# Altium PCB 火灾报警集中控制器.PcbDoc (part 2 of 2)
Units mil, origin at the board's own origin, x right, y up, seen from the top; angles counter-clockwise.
Board outline 3890 x 3920 mil, 2 copper layers (Top Layer, Bottom Layer); 74 components, 132 nets, 502 pads, 181 vias.
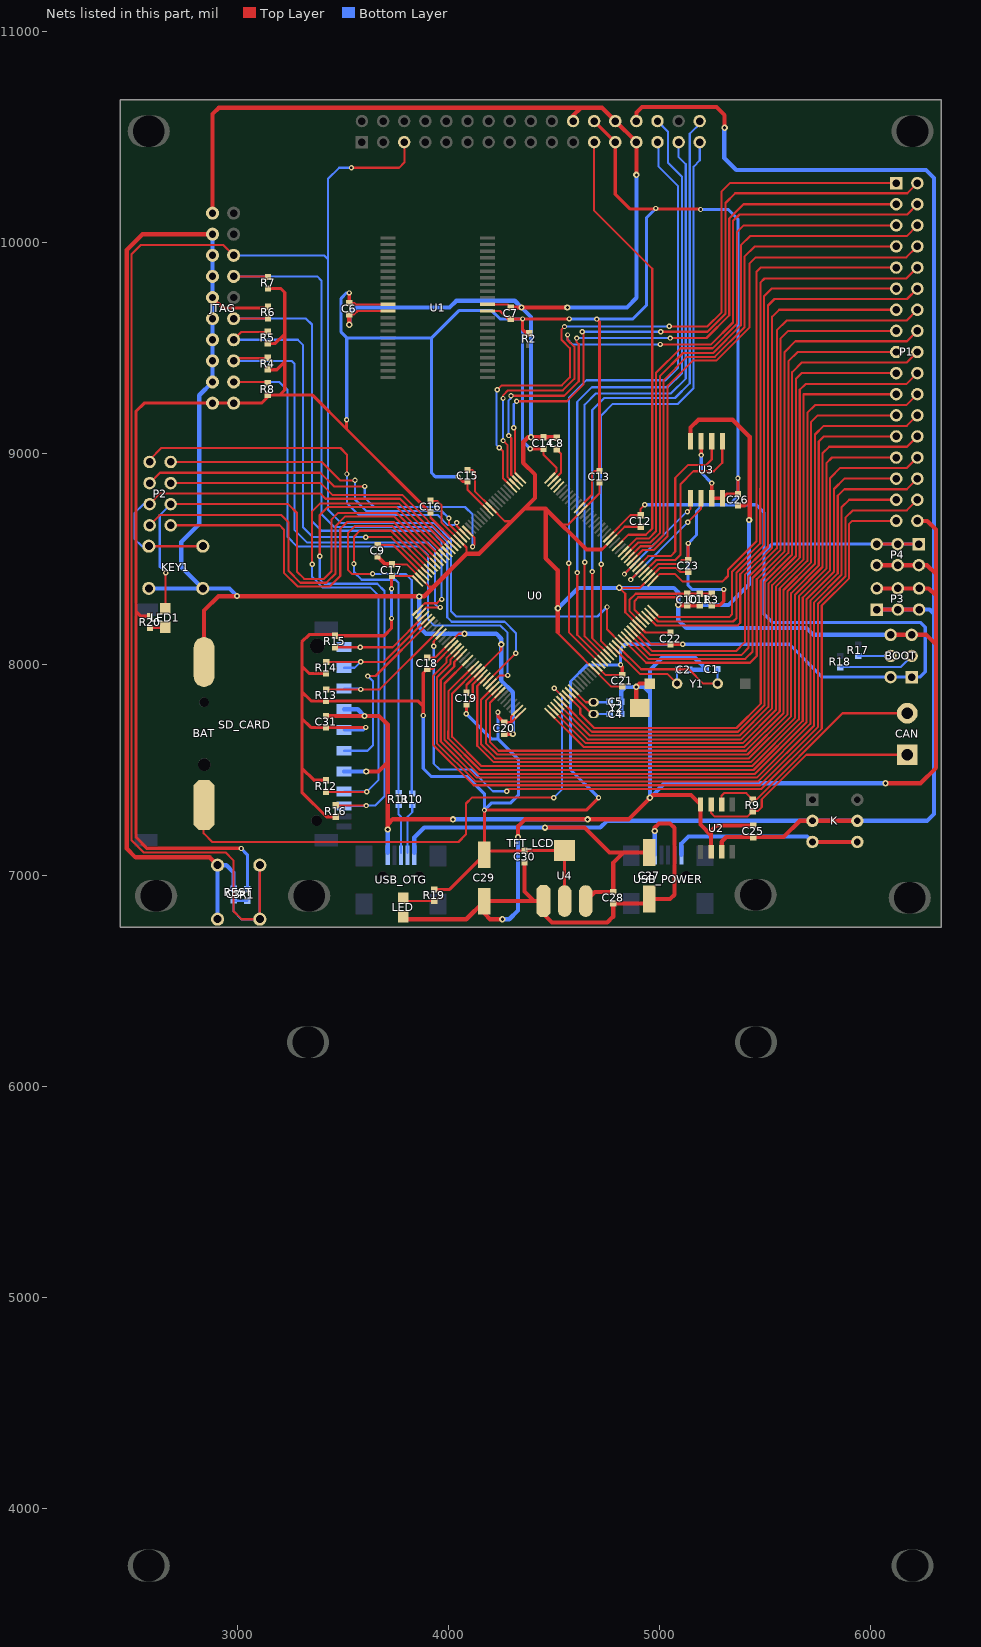
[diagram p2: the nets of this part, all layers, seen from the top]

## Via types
v1: diameter 25, hole 12, Top Layer to Bottom Layer, 154 vias
v2: diameter 30, hole 15, Top Layer to Bottom Layer, 27 vias

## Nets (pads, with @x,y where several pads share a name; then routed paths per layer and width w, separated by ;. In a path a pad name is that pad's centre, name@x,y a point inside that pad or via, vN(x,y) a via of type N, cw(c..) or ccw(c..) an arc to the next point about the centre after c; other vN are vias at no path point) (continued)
GND: BAT.2 BOOT.5 BOOT.6 C1.1 C2.1 C3.1 C4.2 C5.2 C6.1 C7.1 C8.2 C9.2 C10.1 C11.1 C12.1 C13.1 C14.1 C15.1 C16.1 C17.1 C18.1 C19.1 C20.1 C21.1 C22.1 C23.1 C25.2 C26.1 C27.2 C28.1 C29.2 C30.1 C31.1 JTAG.4 JTAG.6 JTAG.8 JTAG.10 JTAG.12 JTAG.14 JTAG.16 JTAG.18 JTAG.20 KEY1.1 LED.2 P1.34 P3.2 P3.4 P3.6 P4.2 P4.4 P4.6 R6.1 REST.1 SD_CARD.3 SD_CARD.6 TFT_LCD.22 TFT_LCD.26 TFT_LCD.27 U0.16 U0.31 U0.38 U0.51 U0.61 U0.83 U0.94 U0.107 U0.120 U0.130 U1.12 U1.34 U2.2 U2.8 U3.4 U4.1 USB_OTG.5 USB_POWER.5 Y1.@4952.56,7910 Y2. | length 35244.4
  Top Layer w10: C6.1@3530,9659 3553,9659 3568.94,9674.94 U1.34@3712.91,9674.94 ; C17.1@3732,8475 3802.81,8475 U0.107@3867.78,8410.03 3908.81,8369 3929.94,8369 ; C18.1@3899,8034 3937.18,8034 4049.18,8146 v2(4076,8146) ; C16.1@3915,8776 3946,8776 3966,8756 3966,8673.71 U0.94@4048.73,8590.98 4085,8554.71 4085,8525 ; C19.1@4085,7867 4085,7903.44 4250,8068.44 v2(4250,8096) ; C15.1@4090,8922 4113,8922 4125,8910 4125,8820.94 U0.83@4201.85,8744.09 4266.94,8679 4297,8679 ; U1.12@4185.35,9706.43 4280.57,9706.43 C7.1@4295,9692 ; 4513.27,8154.27 4771.55,7896 C21.1@4823,7896 ; 4534,8664 4567.18,8664 U0.61@4633.35,8730.17 4715,8811.82 C13.1@4715,8863 ; 4722.22,8543 4724.57,8543 U0.51@4772.54,8590.98 4834.57,8653 C12.1@4910,8653 ; v2(4809,8364) 4837,8336 4837,8248.13 U0.31@4897.82,8187.31 4933.13,8152 C22.1@5052,8152 ; v2@4810,8363.53 4907,8363.53 U0.38@4953.49,8410.03 5001.47,8458 5080,8458 5099,8439 C23.1@5141,8439
  Top Layer w15: JTAG.12@2882,9739 2931,9690 R6.1@3139,9690 ; R6.1@3148.5,9699.5 R6.1@3152,9696
  Top Layer w20: BAT.2@2842,8012.52 2842,8256 2910,8324 3884.94,8324 3929.94,8369 4085.94,8525 ; JTAG.18@2882,10039 2551,10039 2476,9964 2476,7129 2518,7087 2868.91,7087 REST.1@2906,7049.91 ; JTAG.20@2882,10139 2882,10608 2912,10638 4727,10638 TFT_LCD.26@4790,10575 TFT_LCD.27@4890,10475 v2(4890,10320) ; R6.1@3139,9690 R6.1@3145,9696 ; C31.1@3420,7757 v2(3602,7757) 3671,7757 3712.01,7715.99 3712.01,7537.01 ; v2(3530,9610) C6.1@3530,9659 ; v2(3610.54,7493.54) 3668.54,7493.54 3712.01,7537.01 ; C9.2@3663.94,8512.5 3701.44,8475 C17.1@3732,8475 ; v2(3712.01,7219) 3712.01,7244.01 ; LED.2@3780.94,6793.96 4084.2,6793.96 C29.2@4170,6879.76 ; v2@4020,7268 3736,7268 3712.01,7244.01 ; 4085,8525 4085.94,8525 ; v2(4255,6794) 4197,6794 4170,6821 C29.2@4170,6879.76 ; C20.1@4264,7671 v2(4305,7671) ; C7.1@4295,9692 v2(4346,9692) v2(4563,9692) ; v2(4329,7182) 4329,7234 4362,7267 v2(4659,7267) 4852,7267 v2(4954,7369) 4968,7383 5148.41,7383 U2.8@5194,7337.41 5194,7242 5244,7192 ; C30.1@4360,7063 4360,6924.76 4405,6879.76 ; 4457,8740 4360,8740 ; C8.2@4511.56,9077 C14.1@4450,9077 v2(4391,9077) 4376,9077 4354,9055 4354,8956 4410,8900 4410,8790 4360,8740 ; 4517.34,8154.89 4517.34,8446.66 4460.5,8503.5 4460.5,8738 4653.15,8545.35 4722.22,8545.35 ; TFT_LCD.22@4590,10575 4590,10601 4624,10635 ; Y2.@4907,7795 4889,7813 v2(4889,7894.56) 4904.44,7910 Y1.@4952.56,7910 ; v2(4977.01,7211.99) 4977.01,7228.01 4997,7248 5049,7248 5070,7227 5070,6910 5049.76,6889.76 C27.2@4950,6889.76 4928.24,6868 C28.1@4780,6868 4780,6806 4752,6778 4490,6778 4450.03,6817.97 U4.1@4450.03,6879.94 4449.86,6879.76 4405,6879.76 ; v2@5088,8281 C10.1@5131,8281 C11.1@5189,8281 ; U3.4@5146.94,9058 5146.94,9122.94 5184,9160 5346,9160 5427,9079 5427,8779 ; U2.2@5244,7113 5244,7192 ; C26.1@5371,8754 5402,8754 5427,8779 ; v2@5427,8693 5427,8779 ; C25.2@5443.06,7237.5 5269.5,7237.5 5244,7212 5244,7192 ; P4.6@6028,8471 P4.4@6128,8471 P4.2@6228,8471 6267,8471 6309,8429 ; P3.2@6029,8361 P3.4@6129,8361 P3.6@6229,8361 6275,8361 6309,8327 ; v2(6070,7438) 6236,7438 6309,7511 6309,8095 ; BOOT.6@6094,8142 6262,8142 6309,8095 ; P1.34@6221,8681 6268,8681 6309,8640 6309,8429 ; 3712.01,7244.01 3712.01,7537.01 ; 4085.94,8525 4145,8525 4360,8740 ; C29.2@4170,6879.76 4405,6879.76 ; 6309,8095 6309,8327 ; 6309,8327 6309,8429
  Bottom Layer w20: KEY1.1@2580.09,8361 KEY1.1@2836,8361 ; JTAG.18@2882,10039 JTAG.16@2882,9939 JTAG.14@2882,9839 JTAG.12@2882,9739 JTAG.10@2882,9639 JTAG.8@2882,9539 JTAG.6@2882,9439 JTAG.4@2882,9339 2819,9276 2819,8666 2734,8581 2734,8463 KEY1.1@2836,8361 ; REST.1@2906,6794 REST.1@2906,7049.91 2947.09,7049.91 2982,7015 C3.1@2982,6939 ; v2(2998,8325) 2962,8361 KEY1.1@2836,8361 ; SD_CARD.6@3504.64,7493.54 v2(3610.54,7493.54) ; SD_CARD.3@3504.64,7788.82 3570.18,7788.82 v2(3602,7757) ; v2(3530,9610) 3530,9660 3562,9692 4005,9692 4037,9724 4314,9724 v2(4346,9692) 4391,9647 v2(4391,9077) ; USB_OTG.5@3712.01,7109.06 v2(3712.01,7219) ; v2(3861,8323) 3861,8178 3893,8146 4226.47,8146 4250,8122.47 v2(4250,8096) 4249.5,8095.5 4249.5,7924.5 4305,7869 v2(4305,7671) ; v2@4021,7268 4658,7268 v2(4659,7267) ; v2(4255,6794) 4288,6794 4329,6835 v2(4329,7182) ; v2(4518,8267) 4614.53,8363.53 5067.47,8363.53 5088,8343 v2(5088,8283) ; v2(4563,9692) 4845,9692 4891,9738 v2@4891,10320 ; C4.2@4818.5,7766.06 C5.2@4818.5,7824.06 4818.5,7875.5 4837.56,7894.56 v2(4889,7894.56) 4926.44,7894.56 4954,7867 ; USB_POWER.5@4977.01,7099.06 v2(4977.01,7211.99) ; C2.1@5142,7976 C1.1@5217,7976 ; C1.1@5220,7979 5164,8035 5014,8035 4954,7975 4954,7867 ; v2(5424,8685) 5424,8380 5327,8283 v2(5088,8283) ; v2(6070,7438) 5023,7438 v2(4954,7369) 4954,7867 ; BOOT.6@6094,8141 5729,8141 5696.5,8173.5 5126.5,8173.5 5088,8212 v2(5088,8283)
  other v2: 4021,7267
GT_INT: TFT_LCD.29 U0.18 | length 2998.6
  Top Layer w10: v1(4570,8480) 4570,8153.23 U0.18@4716.86,8006.36
  Bottom Layer w10: v1(4570,8480) 4570,9264 4653,9347 5028,9347 5088,9407 5088,10267 4994,10361 TFT_LCD.29@4994,10471
GT_MISO: TFT_LCD.33 U0.22 | length 2807.6
  Top Layer w10: v1(4723,8476) 4723,8111.58 U0.22@4772.54,8062.04
  Bottom Layer w10: v1(4723,8476) 4723,9180 4778,9235 5087,9235 5160,9308 5160,9324.54 5161,9325.54 5161,10359 5190.5,10388.5 ; 5190,10389 TFT_LCD.33@5190,10475
GT_RST: TFT_LCD.30 U0.19 | length 3069.1
  Top Layer w10: v1(4610,8436) 4610,8141.06 U0.19@4730.78,8020.28
  Bottom Layer w10: v1(4610,8436) 4610,9245 4679,9314 5039,9314 5106,9381 5106,10311 5040,10377 5040,10525 TFT_LCD.30@4990,10575
GT_SCL: TFT_LCD.31 U0.20 | length 2903
  Top Layer w10: v1(4645,8485) 4645,8133.9 U0.20@4744.7,8034.2
  Bottom Layer w10: v1(4645,8485) 4645,9231 4699,9285 5054,9285 5124,9355 5124,10371 5089,10406 TFT_LCD.31@5089,10475
GT_SDA: TFT_LCD.34 U0.21 | length 2962.3
  Top Layer w10: v1(4681,8441) 4681,8125.74 U0.21@4758.62,8048.12
  Bottom Layer w10: v1(4681,8441) 4681,9206 4738,9263 5073,9263 5143,9333 5143,10515 TFT_LCD.34@5196.5,10568.5
JTCK: JTAG.9 R6.2 U0.109 | length 2546.5
  Top Layer w10: JTAG.9@2982,9639 R6.2@3149.44,9639 ; U0.109@3853.86,8256.91 3888,8291 3944.94,8291 3962.94,8309 v1(3968,8309)
  Bottom Layer w10: JTAG.9@2982,9639 3325,9639 3353,9611 3353,8679 3398,8634 3917.63,8634 3967,8584.63 v1@3967,8309
JTDI: JTAG.5 R4.2 U0.110 | length 2355.6
  Top Layer w10: JTAG.5@2982,9439 2994.5,9451.5 R4.2@3152.06,9451.5 ; U0.110@3867.78,8242.99 3895.79,8271 v1(3961,8271)
  Bottom Layer w10: JTAG.5@2982,9439 3256,9439 3271,9424 3271,8637 3330,8578 3903,8578 3936,8545 3936,8286 3951,8271 v1(3961,8271)
JTDO: JTAG.13 R7.2 U0.133 | length 3333.1
  Top Layer w10: JTAG.13@2982,9839 R7.2@3149.56,9839 ; U0.133@4187.93,7922.85 v1(4318.54,8053.46)
  Bottom Layer w10: JTAG.13@2982,9839 3378,9839 3398,9819 3398,8712 3458,8652 3925.09,8652 3994,8583.09 3994,8224 4015,8203 4266,8203 4320,8149 v1@4320,8065
JTMS: JTAG.7 R5.2 U0.105 | length 2060.9
  Top Layer w10: JTAG.7@2982,9539 3019.5,9576.5 R5.2@3152.06,9576.5 ; v1(3608,8604) 3729.48,8604 U0.105@3895.62,8437.87
  Bottom Layer w10: JTAG.7@2982,9539 3286,9539 3310,9515 3310,8652 3358,8604 v1(3608,8604)
JTRST: JTAG.3 R8.2 U0.134 | length 2844
  Top Layer w10: JTAG.3@2982,9339 3144.56,9339 R8.2@3152.06,9331.5 ; U0.134@4201.85,7908.93 4201.93,7908.93 4242,7949 v1(4280,7949)
  Bottom Layer w10: JTAG.3@2982,9339 3199,9339 3237,9301 3237,8606 3284,8559 3861,8559 3903,8517 3903,8215 3933,8185 4246,8185 4280,8151 v1(4280,7949)
LCD_BL: TFT_LCD.23 U0.49 | length 2142.4
  Top Layer w10: TFT_LCD.23@4690,10475 4690,10150.46 4965,9875.46 4965,8645 4935,8615 4852.24,8615 U0.49@4800.38,8563.14
NetBOOT_3: BOOT.3 R18.2 | length 358.4
  Bottom Layer w10: R18.2@5857.56,7988 6141,7988 BOOT.3@6194,8041
NetBOOT_4: BOOT.4 R17.1 | length 153
  Bottom Layer w10: R17.1@5941,8041 BOOT.4@6094,8041
NetC8_1: C8.1 U0.71 | length 172.6
  Top Layer w10: U0.71@4494.15,8869.36 4533,8908.21 4533,8999 C8.1@4514,9018
NetC9_1: C9.1 U0.106 | length 277
  Top Layer w10: C9.1@3664,8567 3738.64,8567 U0.106@3881.7,8423.95
NetCAN_1: CAN.1 R9.1 U2.7 | length 1119.4
  Top Layer w10: U2.7@5244,7337.41 5244,7297 5261,7280 5415,7280 R9.1@5441,7306 5465,7306 5484,7325 5484,7361.8 5695.2,7573 CAN.1@6173,7573
NetCAN_2: CAN.2 R9.2 U2.6 | length 1108.3
  Top Layer w10: U2.6@5294,7337.41 5294,7380 5305,7391 5410.56,7391 R9.2@5441.06,7360.5 5457.25,7360.5 5866.6,7769.85 CAN.2@6173,7769.85
NetLED1_1: LED1.1 R20.2 | length 69.6
  Top Layer w10: R20.2@2585.94,8174.5 LED1.1@2655.53,8174.5
NetLED_1: LED.1 R19.2 | length 151.5
  Top Layer w10: LED.1@3780.94,6880.97 R19.2@3932.47,6880.97
NetR10_1: R10.1 USB_OTG.2 | length 234.9
  Bottom Layer w10: USB_OTG.2@3806.5,7109.06 3806.5,7279.5 3828,7301 R10.1@3828,7335
NetR11_1: R11.1 USB_OTG.3 | length 231.5
  Bottom Layer w10: R11.1@3764,7336 3764,7290 3775,7279 USB_OTG.3@3775,7109.06
OSC32_IN: C4.1 U0.8 Y2.2 | length 229.4
  Top Layer w10: U0.8@4577.67,7867.17 4678.84,7766 Y2.2@4687,7766 ; Y2.2@4688.84,7756 Y2.2@4690,7756
  Bottom Layer w10: Y2.2@4687,7766 C4.1@4764,7766
OSC32_OUT: C5.1 U0.9 Y2.1 | length 194.9
  Top Layer w10: U0.9@4591.59,7881.09 4650.68,7822 Y2.1@4687,7822
  Bottom Layer w10: Y2.1@4687,7822 C5.1@4762,7822
OSC_IN: C2.2 U0.23 Y1.2 | length 446.6
  Top Layer w10: U0.23@4786.46,8075.96 4906.42,7956 5036.87,7956 Y1.2@5082.87,7910
  Bottom Layer w10: C2.2@5082.87,7971.31 Y1.2@5082.87,7910 Y1.2@5103,7910
OSC_OUT: C1.2 U0.24 Y1.1 | length 617.7
  Top Layer w10: U0.24@4800.38,8089.88 4912.26,7978 5139,7978 5207,7910 Y1.1@5275,7910
  Bottom Layer w10: Y1.1@5275,7910 C1.2@5275,7978.56
PA0: P1.12 U0.34 | length 2763.6
  Top Layer w10: U0.34@4939.57,8229.07 4982.65,8186 5370,8186 5382,8198 5382,8428.57 5513.18,8559.75 5513.18,9701.18 5544,9732 6172,9732 P1.12@6221,9781
PA1: P1.11 U0.35 | length 2653.9
  Top Layer w10: U0.35@4953.49,8242.99 4992.48,8204 5348,8204 5364,8220 5364,8436.03 5495.18,8567.2 5495.18,9746 5530.18,9781 P1.11@6121,9781
PA2: P1.10 U0.36 | length 2794.4
  Top Layer w10: U0.36@4967.41,8256.91 4999.32,8225 5330,8225 5343,8238 5343,8440.48 5477,8574.48 5477,8834.46 5477.18,8834.63 5477.18,9809 5497.18,9829 6169,9829 P1.10@6221,9881
PA3: P1.9 U0.37 | length 2563.9
  Top Layer w10: U0.37@4967.41,8396.1 5001.31,8430 5072,8430 5109,8393 5297,8393 5324,8420 5324,8448.65 5459,8583.65 5459,8841.91 5459.18,8842.09 5459.18,9860.46 5479.72,9881 P1.9@6121,9881
PA4: U0.40 U3.1 | length 883.6
  Top Layer w10: U0.40@4925.65,8437.86 4982.79,8495 5073,8495 5099,8521 5099,8855 5160,8916 5257,8916 5297,8956 U3.1@5297,9058
PA5: U0.41 U3.6 | length 591.8
  Top Layer w10: v1(4862.95,8403) U0.41@4911.74,8451.78 ; v1(5133,8675) 5197,8739 U3.6@5197,8788
  Bottom Layer w10: v1(4862.95,8403) v1@5133.98,8674.02
PA6: U0.42 U3.2 | length 849.3
  Top Layer w10: U0.42@4897.82,8465.7 4946.11,8514 5052,8514 5074,8536 5074,8885 5134,8945 5220,8945 5246.94,8971.94 U3.2@5246.94,9058
PA7: U0.43 U3.5 | length 556.9
  Top Layer w10: v1(4833.27,8429) U0.43@4883.9,8479.62 ; v1@5134.5,8726.5 5147,8739 U3.5@5147,8788
  Bottom Layer w10: v1(4833.27,8429) v1@5129.27,8725
  other v1: 5132,8724
PA8: LED1.2 P2.6 U0.100 | length 2480.2
  Top Layer w10: LED1.2@2659.06,8265.04 v1@2659.06,8435 ; P2.6@2684,8760 3240,8760 3282,8718 3282,8440 3316,8406 3410,8406 3445,8441 3445,8687 3477,8719 3753.68,8719 U0.100@3965.21,8507.46
  Bottom Layer w10: v1(2660,8435) 2632,8463 2632,8708 P2.6@2684,8760
PA9: P2.7 U0.101 | length 2002.4
  Top Layer w10: P2.7@2584,8660 2632,8708 3209,8708 3242,8675 3242,8444 3298,8388 3421,8388 3465,8432 3465,8657 3509,8701 3743.84,8701 U0.101@3951.3,8493.54
PA10: P2.8 U0.102 | length 1831.5
  Top Layer w10: P2.8@2684,8660 3200,8660 3220,8640 3220,8435 3285,8370 3437,8370 3487,8420 3487,8643 3519,8675 3742,8675 U0.102@3937.38,8479.62
PA11: R10.2 U0.103 | length 1999.7
  Top Layer w10: v1(3640,8430) 3542,8430 3523,8449 3523,8623 3556,8656 3734,8656 3734,8655.16 U0.103@3923.46,8465.7
  Bottom Layer w10: v1(3640,8430) 3796,8430 3825.94,8400.06 R10.2@3825.94,7391
PA12: R11.2 U0.104 | length 1839.7
  Top Layer w10: v1(3552,8478) 3552,8606 3580,8634 3727.32,8634 U0.104@3909.54,8451.78
  Bottom Layer w10: v1(3552,8478) 3552,8439 3589,8402 3749,8402 3762.94,8388.06 R11.2@3762.94,7392
PB0: P1.6 U0.46 | length 2682.7
  Top Layer w10: U0.46@4842.14,8521.38 4899.76,8579 4957,8579 5001,8623 5001,9366 5111,9476 5253.91,9476 5385,9607.09 5385,9987 5428,10030 6170,10030 P1.6@6221,10081
PB1: P1.5 U0.47 | length 2626.9
  Top Layer w10: U0.47@4828.22,8535.3 4889.92,8597 4948,8597 4983,8632 4983,9382 5100,9499 5251.46,9499 5366,9613.54 5366,10048 5399,10081 P1.5@6121,10081
PB5: P1.25 U0.135 | length 3609.8
  Top Layer w10: U0.135@4215.77,7895.01 4154,7833.24 4154,7623 4221,7556 5423.65,7556 5623,7755.35 5623,8338.65 5754,8469.65 5754,9057 5778,9081 P1.25@6121,9081
PB6: P1.24 U0.136 | length 3707.9
  Top Layer w10: U0.136@4229.69,7881.09 4177,7828.4 4177,7627.54 4230.54,7574 5416.19,7574 5605,7762.81 5605,8346.1 5736,8477.1 5736,9090 5777,9131 6171,9131 P1.24@6221,9181
PB7: P1.23 U0.137 | length 3584.1
  Top Layer w10: U0.137@4243.6,7867.17 4197,7820.57 4197,7633 4238,7592 5408.73,7592 5587,7770.27 5587,8353.56 5718,8484.56 5718,9150 5749,9181 P1.23@6121,9181
PB10: U0.69
PB11: U0.70
PB12: P1.2 U0.73 | length 3171
  Top Layer w10: v1(4309,9122) 4315,9116 4315,8909.33 U0.73@4341.04,8883.29 ; v1(4322.5,9247.5) 4560,9247.5 4639,9326.5 4639,9572 v1(4634,9577) ; v1(5005,9577) 5226.96,9577 5312,9662.04 5312,10187 5358,10233 6173,10233 P1.2@6221,10281
  Bottom Layer w10: v1(4309,9122) 4309,9234 v1(4322.5,9247.5) ; v1(4634,9577) v1(5005,9577)
PB13: P1.3 U0.74 | length 3031.1
  Top Layer w10: v1(4285,9085) 4297,9073 4297,8899.49 U0.74@4327.12,8869.37 ; v1(4296,9273.5) 4548,9273.5 4617,9342.5 4617,9518 4607,9528 v1(4607,9547) ; v1(5050,9547) 5222.41,9547 5330,9654.59 5330,10113.54 5397.46,10181 P1.3@6121,10181
  Bottom Layer w10: v1(4285,9085) 4283.5,9086.5 4283.5,9249.94 4296,9262.44 v1(4296,9273.5) ; v1(4607,9547) v1(5050,9547)
PB14: P1.4 U0.75 | length 3279.3
  Top Layer w10: v1(4258.5,9061.5) 4279,9041 4279,8889.65 U0.75@4313.2,8855.45 ; v1(4258.5,9261) 4258.5,9275.5 4282,9299 4541,9299 4596,9354 4596,9506 4564,9538 v1(4564,9562) ; v1(5003,9517) 5244,9517 5348,9621 5348,10102 5378.5,10132.5 6172.5,10132.5 P1.4@6221,10181
  Bottom Layer w10: v1(4258.5,9061.5) v1(4258.5,9261) ; v1(4564,9562) 4564,9540 4587,9517 v1(5003,9517)
PB15: P1.1 U0.76 | length 3310.2
  Top Layer w10: v1(4231.5,9302.5) 4252,9323 4537,9323 4575,9361 4575,9499 4536,9538 4536,9588 v1(4549.5,9601.5) ; v1(4241,9027) 4258,9010 4258,8882.81 U0.76@4299.28,8841.53 ; v1(5046,9602.5) 5227,9602.5 5294,9669.5 5294,10242 5333,10281 P1.1@6121,10281
  Bottom Layer w10: v1(4231.5,9302.5) 4228,9299 4228,9040 v1(4241,9027) ; v1(4549.5,9601.5) 4550.5,9602.5 v1(5046,9602.5)
PC0: P1.16 U0.26 | length 2855.2
  Top Layer w10: U0.26@4828.22,8117.72 4936.94,8009 5428,8009 5460,8041 5460,8404.75 5592,8536.75 5592,9481 5643,9532 6172,9532 P1.16@6221,9581
PC1: P1.15 U0.27 | length 2757.3
  Top Layer w10: U0.27@4842.14,8131.64 4946.78,8027 5406,8027 5440,8061 5440,8410.2 5573.34,8543.54 5573.34,9545.34 5609,9581 P1.15@6121,9581
PC2: P1.14 U0.28 | length 2886.2
  Top Layer w10: U0.28@4856.06,8145.56 4956.62,8045 5386,8045 5422,8081 5422,8417.66 5555.34,8551 5555.34,9583.34 5602,9630 6170,9630 P1.14@6221,9681
PC3: P1.13 U0.29 | length 2788
  Top Layer w10: U0.29@4869.98,8159.48 4965.45,8064 5362,8064 5404,8106 5404,8425.12 5533,8554.12 5533,9647.82 5566.18,9681 P1.13@6121,9681
PC4: P1.8 U0.44 | length 2561.6
  Top Layer w10: U0.44@4869.98,8493.54 4919.43,8543 4971.91,8543 5038,8609.09 5038,9321 5157,9440 5268.82,9440 5425,9596.18 5425,9899 5455,9929 6169,9929 P1.8@6221,9981
PC5: P1.7 U0.45 | length 2500.2
  Top Layer w10: U0.45@4856.06,8507.46 4909.6,8561 4964.46,8561 5019,8615.54 5019,9348 5129,9458 5261.37,9458 5403,9599.63 5403,9934 5450,9981 P1.7@6121,9981
PC6: P2.4 U0.96 | length 1459.9
  Top Layer w10: P2.4@2684,8860 3394,8860 3450,8804 3780.03,8804 U0.96@4020.89,8563.14
PC7: KEY1.2 P2.5 U0.97 | length 2101.3
  Top Layer w10: KEY1.2@2580.09,8561 KEY1.2@2836,8561 ; P2.5@2584,8760 2635,8811 3392,8811 3417,8786 3770.19,8786 U0.97@4006.97,8549.22
  Bottom Layer w10: KEY1.2@2580.09,8561 2548,8561 2512,8597 2512,8717 2555,8760 P2.5@2584,8760
PC8: R12.2 SD_CARD.7 U0.98 | length 2667.3
  Top Layer w10: v1(3354,8475) 3354,8726 3392,8764 3764.35,8764 U0.98@3993.05,8535.3 ; R12.2@3418.44,7396 R12.2@3419.94,7397.5 v1(3612.5,7397.5)
  Bottom Layer w10: v1(3354,8475) 3354,8415.54 3404.54,8365 3631,8365 3669,8327 3669,7454 v1(3612.5,7397.5) 3611.93,7398.07 SD_CARD.7@3504.64,7398.07
PC9: R16.2 SD_CARD.8 U0.99 | length 2659.2
  Top Layer w10: v1(3390,8513) 3390,8709 3427,8746 3754.52,8746 U0.99@3979.14,8521.38 ; R16.2@3466.06,7332.5 v1(3610.5,7332.5)
  Bottom Layer w10: v1(3390,8513) 3390,8405 3412,8383 3663,8383 3697,8349 3697,7377 3652.5,7332.5 v1(3610.5,7332.5) 3609,7331 SD_CARD.8@3505,7331
PC10: R15.2 SD_CARD.9 U0.111 | length 555.7
  Top Layer w10: R15.2@3461.94,8082.5 3735.13,8082.5 U0.111@3881.7,8229.07
  Bottom Layer w10: SD_CARD.9@3504.64,8084.09 v1@3579.91,8084.09
  other v1: 3582,8082
PC11: R14.2 SD_CARD.1 U0.112 | length 650.5
  Top Layer w10: R14.2@3420.06,8012.5 3692.97,8012.5 U0.112@3895.62,8215.15
  Bottom Layer w10: SD_CARD.1@3505,7985 3555,7985 v1(3584,8014)
PC12: SD_CARD.5 U0.113 | length 884.8
  Top Layer w10: v1(3617,7946) 3654.3,7946 U0.113@3909.54,8201.23
  Bottom Layer w10: SD_CARD.5@3504.64,7591.97 3615.97,7591.97 3642,7618 3642,7921 v1(3617,7946)
PC13: P1.17 U0.7 | length 3247.7
  Top Layer w10: U0.7@4563.75,7853.25 4624,7793 4624,7766 4690,7700 5364,7700 5479,7815 5479,8398.29 5610,8529.29 5610,9437 5654,9481 P1.17@6121,9481
PD2: R13.2 SD_CARD.2 U0.116 | length 726.8
  Top Layer w10: R13.2@3420.06,7882.5 v1(3584,7882.5) 3674.32,7882.5 U0.116@3951.3,8159.48
  Bottom Layer w10: SD_CARD.2@3505,7887 3579.5,7887 v1(3584,7882.5)
PD3: P1.33 U0.117 | length 3897.2
  Top Layer w10: v1(3930,8087) 3930,8110.34 U0.117@3965.22,8145.56 ; v1(4276,7400) 4286.72,7410.72 5482.01,7410.72 5768,7696.71 5768,8280 5898,8410 5898,8667 5912,8681 P1.33@6121,8681
  Bottom Layer w10: v1(3930,8087) 3930,7531 3958,7503 4107,7503 4210,7400 v1(4276,7400)
PD6: P1.32 U0.122 | length 3938.5
  Top Layer w10: U0.122@4034.81,8075.96 3991,8032.15 3991,8010.46 3926,7945.46 3926,7621.9 4119.18,7428.72 5474.56,7428.72 5750,7704.16 5750,8287.46 5880,8417.46 5880,8695 5916,8731 6171,8731 P1.32@6221,8781
PD7: P1.31 U0.123 | length 3809.8
  Top Layer w10: U0.123@4048.73,8062.04 4009,8022.31 4009,8003 3945,7939 3945,7628.35 4126.63,7446.72 5467.1,7446.72 5732,7711.62 5732,8294.91 5862,8424.91 5862,8745 5898,8781 P1.31@6121,8781
PE2: P1.22 U0.1 | length 3251.4
  Top Layer w10: U0.1@4480.23,7769.73 4639.97,7610 5401.28,7610 5569,7777.72 5569,8361.01 5700,8492.01 5700,9193 5736,9229 6169,9229 P1.22@6221,9281
PE3: P1.21 U0.2 | length 3174.9
  Top Layer w10: U0.2@4494.15,7783.65 4649.81,7628 5393.82,7628 5551,7785.18 5551,8368.47 5682,8499.47 5682,9280 5683,9281 P1.21@6121,9281
PE4: P1.20 U0.3 | length 3301.8
  Top Layer w10: U0.3@4508.07,7797.57 4659.64,7646 5386.37,7646 5533,7792.63 5533,8375.93 5664,8506.93 5664,9302 5691,9329 6169,9329 P1.20@6221,9381
PE5: P1.19 U0.4 | length 3205.4
  Top Layer w10: U0.4@4521.99,7811.49 4669.48,7664 5378.91,7664 5515,7800.09 5515,8383.38 5646,8514.38 5646,9355 5672,9381 P1.19@6121,9381
PE6: P1.18 U0.5 | length 3337
  Top Layer w10: U0.5@4535.91,7825.41 4679.32,7682 5371.46,7682 5497,7807.54 5497,8390.84 5628,8521.84 5628,9385 5674,9431 6171,9431 P1.18@6221,9481
PG6: P2.3 U0.91 | length 1907.7
  Top Layer w10: P2.3@2584,8860 2633,8909 3393,8909 3458,8844 v1(3603,8844) ; U0.91@4090.49,8632.74 4123,8600.23 4123,8568 v1(4114,8559) v1@4113,8558
  Bottom Layer w10: v1(3603,8844) 3603,8791 3647,8747 4078,8747 4114,8711 v1(4114,8559)
PG7: P2.1 U0.92 | length 1840.8
  Top Layer w10: P2.1@2584,8960 2584,8970 2640,9026 3488,9026 3519,8995 v1@3519,8911 ; v1(4039,8673) 4039,8656.39 U0.92@4076.57,8618.82
  Bottom Layer w10: v1(3519,8903) 3519,8765 3575,8709 3949,8709 3997,8661 4027,8661 v1(4039,8673)
PG8: P2.2 U0.93 | length 1595.1
  Top Layer w10: P2.2@2684,8960 3399,8960 3486,8873 v1(3557,8873) ; v1(4002,8693) 4002,8665.55 U0.93@4062.65,8604.9
  Bottom Layer w10: v1(3557,8873) 3557,8782 3611,8728 3967,8728 v1(4002,8693)
PG9: P1.30 U0.124 | length 3926.1
  Top Layer w10: U0.124@4062.65,8048.12 4027,8012.47 4027,7991 3963,7927 3963,7635.81 4134.09,7464.72 5459.65,7464.72 5714,7719.07 5714,8302.37 5844,8432.37 5844,8800 5875,8831 6171,8831 P1.30@6221,8881
PG11: P1.29 U0.126 | length 3779.5
  Top Layer w10: U0.126@4090.49,8020.28 3981,7910.79 3981,7643.27 4141.54,7482.72 5452.19,7482.72 5696,7726.53 5696,8309.82 5826,8439.82 5826,8832 5875,8881 P1.29@6121,8881
PG13: P1.28 U0.128 | length 3885.9
  Top Layer w10: U0.128@4118.33,7992.44 3999.18,7873.3 3999.18,7686.18 3999,7686 3999,7650.72 4149,7500.72 5444.73,7500.72 5678,7733.99 5678,8317.28 5808,8447.28 5808,8884 5856,8932 6172,8932 P1.28@6221,8981
PG14: P1.27 U0.129 | length 3768.5
  Top Layer w10: U0.129@4132.25,7978.52 4017.18,7863.46 4017.18,7657.99 4155.18,7520 5438.56,7520 5660,7741.44 5660,8324.73 5790,8454.73 5790,8954 5817,8981 P1.27@6121,8981
PG15: P1.26 U0.132 | length 3750.5
  Top Layer w10: U0.132@4174.01,7936.77 4136,7898.76 4136,7615.54 4213.54,7538 5431.1,7538 5642,7748.9 5642,8332.19 5772,8462.19 5772,9001 5803,9032 6172,9032 P1.26@6221,9081
RESET: C3.2 JTAG.15 R1.2 REST.2 TFT_LCD.5 U0.25 | length 9427.2
  Top Layer w10: JTAG.15@2982,9939 2933,9988 2542,9988 2499,9945 2499,7167 2556,7110 2944,7110 2981,7073 2981,6833 3020,6794 REST.2@3106,6794 REST.2@3106,7049.91 ; v1(3540,10354) 3766,10354 3791,10379 TFT_LCD.5@3791,10474 ; v1(4751,8273) 4751,8167.1 U0.25@4814.3,8103.8
  Bottom Layer w10: JTAG.15@2982,9939 3410,9939 3429,9920 ; R1.2@3047.06,6881.5 2985.06,6881.5 C3.2@2982.06,6884.5 2982.06,6830.94 3019,6794 REST.2@3106,6794 REST.2@3106,7049.91 ; v1(3540,10354) 3482,10354 3429,10301 3429,9920 ; v1(4751,8273) 4706,8228 4037,8228 4012,8253 4012,8590.54 3932.54,8670 3492,8670 3429,8733 3429,9920
USB_VCC: K.3 K.4 USB_POWER.1 | length 1124
  Top Layer w20: K.3@5724,7160 K.4@5936.6,7160
  Bottom Layer w20: USB_POWER.1@5102.99,7099.06 5102.99,7151.99 5137,7186 5698,7186 K.3@5724,7160 K.4@5936.6,7160
VBAT: BAT.1 U0.6 | length 2573.4
  Top Layer w10: BAT.1@2840,7307 2840,7201 2881,7160 4047,7160 4082,7195 4082,7342 4083,7342 4112,7371 v1@4499,7371 ; v1(4501,7888.16) U0.6@4549.83,7839.33
  Bottom Layer w10: v1(4499,7370) 4537,7408 4537,7852.16 v1(4501,7888.16)
VCC3.3: BOOT.1 BOOT.2 C6.2 C7.2 C12.2 C13.2 C14.2 C15.2 C16.2 C17.2 C18.2 C19.2 C20.2 C21.2 C22.2 C23.2 C26.2 C29.1 C30.2 C31.2 JTAG.1 JTAG.2 P4.1 P4.3 P4.5 R1.1 R2.1 R3.2 R4.1 R5.1 R7.1 R8.1 R12.1 R13.1 R14.1 R15.1 R16.1 R19.1 R20.1 SD_CARD.4 TFT_LCD.24 TFT_LCD.25 U0.17 U0.30 U0.39 U0.52 U0.62 U0.72 U0.84 U0.95 U0.108 U0.121 U0.131 U0.143 U0.144 U1.11 U1.33 U3.3 U3.7 U3.8 U4.2 U4.4 | length 28605.8
  Top Layer w10: C6.2@3530.06,9713.5 3552.5,9713.5 3559.57,9706.43 U1.33@3712.91,9706.43 ; C17.2@3731.94,8420.5 3829.47,8420.5 U0.108@3853.86,8396.11 ; C18.2@3898.94,7979.5 3924.5,7979.5 3939,7994 3939,8007.99 U0.121@4020.89,8089.88 ; C16.2@3914.94,8721.5 3914.94,8696.94 U0.95@4034.81,8577.06 ; C19.2@4084.94,7812.5 4115,7842.56 4115,7905.6 U0.131@4160.09,7950.69 ; C15.2@4089.94,8867.5 4089.94,8828.16 U0.84@4187.93,8730.17 ; U1.11@4185.35,9674.94 4244.06,9674.94 4281.5,9637.5 C7.2@4294.94,9637.5 ; U0.143@4327.12,7783.65 4296.06,7752.6 4296.06,7724.76 U0.144@4341.04,7769.73 ; C14.2@4449.94,9022.5 4449.94,8995.06 4511,8934 4511,8914.05 U0.72@4480.23,8883.28 ; U0.62@4619.43,8744.09 4680,8804.66 ; 4680.5,8806.31 4680.5,8905.5 4692.5,8917.5 C13.2@4715.06,8917.5 ; U0.17@4702.94,7992.44 4745.39,7950 4806.06,7950 ; U0.52@4758.62,8604.9 4861.23,8707.5 C12.2@4910.06,8707.5 4910.06,8738.06 v1(4929,8757) ; U0.30@4883.9,8173.4 4960.79,8096.5 C22.2@5051.94,8096.5 ; U0.39@4939.57,8423.94 4991.63,8476 5086,8476 5104.5,8494.5 C23.2@5135.06,8494.5
  Top Layer w15: R20.1@2586,8229 2542.5,8229 2519.5,8252 ; v1(3018,7129) 3016.5,7130.5 2570.5,7130.5 2519.5,7181.5 2519.5,8252 ; R4.1@3152,9397 3186,9397 3224,9435 ; R5.1@3152,9522 3180,9522 3224,9566 ; R7.1@3152,9782 3205,9782 3224,9763 3224,9566 ; 3200,9277 3224,9301 3224,9435 ; R12.1@3420,7452 3363.5,7452 3305.5,7510 ; R14.1@3420,7958 3340.5,7958 3305.5,7993 ; R15.1@3462,8137 3695,8137 3730,8172 v1(3730,8219) ; R15.1@3462,8142.25 3340.25,8142.25 3305.5,8107.5 3305.5,7993 ; R16.1@3466,7279 3422,7279 3305.5,7395.5 3305.5,7510 ; v1(3517,9160) 3517,9116 ; C6.2@3530.06,9713.5 v1(3530.06,9760.94) ; v1(3608.5,7702.5) C31.2@3419.94,7702.5 3348,7702.5 3305.5,7745 ; v1(3730,8360) C17.2@3730,8418.56 ; v1(3880,7759) 3880,7802 ; C18.2@3898.94,7979.5 3880,7960.56 3880,7802 ; C16.2@3913.22,8719.78 3517,9116 ; R19.1@3933,6935 4005,6935 C29.1@4170,7100 ; v1(4045,8890) 4067.5,8867.5 C15.2@4089.94,8867.5 ; v1@4084.94,7767 C19.2@4084.94,7812.5 ; v1(4234,7775) 4234,7755.56 C20.2@4264.06,7725.5 4295.32,7725.5 ; C7.2@4294.94,9637.5 v1(4351,9637.5) ; R2.1@4383,9570 4368,9570 4351,9587 v1(4351,9637.5) ; v1(4387.5,9022.5) C14.2@4449.94,9022.5 ; U4.2@4550.03,6879.94 U4.4@4550.03,7119.94 4362.5,7119.94 C30.2@4360.06,7117.5 4187.5,7117.5 C29.1@4170,7100 ; v1(4571.5,9637.5) v1(4351,9637.5) ; TFT_LCD.24@4690,10575 TFT_LCD.25@4790,10475 4790,10228 4859,10159 v1@5194,10159 ; v1(4702,9637) 4715.06,9623.94 C13.2@4715.06,8917.5 ; v1(4711,7369) 4653,7311 v1(4170,7311) C29.1@4170,7100 ; v1(4815,7999) 4823.06,7990.94 C21.2@4823.06,7950.5 ; C22.2@5051.94,8096.5 v1(5109.5,8096.5) ; C23.2@5135.06,8494.5 v1(5135.06,8574.06) ; v1(5196.94,8992.94) U3.3@5196.94,9058 ; R3.2@5246.94,8280.5 5284.5,8280.5 5304,8300 v1(5304,8356) ; v1(5247,8860) U3.7@5247,8788 U3.8@5297,8788 5317.5,8808.5 C26.2@5371.06,8808.5 v1(5371.06,8883.06) ; P4.5@6028,8571 P4.3@6128,8571 P4.1@6228,8571 ; 2519.5,8252 2519.5,9200.5 2558,9239 JTAG.2@2882,9239 JTAG.1@2982,9239 3114,9239 3152,9277 3356,9277 3517,9116 ; 3224,9435 3224,9566 ; 3305.5,7510 3305.5,7745 ; 3305.5,7745 3305.5,7871 ; 3305.5,7871 3348.5,7828 R13.1@3420,7828 3854,7828 3880,7802 ; 3305.5,7871 3305.5,7993
  Bottom Layer w15: v1(3018,7129) 3047,7100 R1.1@3047,6936 ; SD_CARD.4@3504.64,7690.39 3596.39,7690.39 v1(3608.5,7702.5) ; v1@3518,9152 3518,9548 ; v1(3530.06,9760.94) 3516.94,9760.94 3491,9735 3491,9575 3518,9548 ; v1(3730,8219) v1(3730,8360) ; v1(3880,7759) 3880,7508 3918,7470 4089,7470 4170,7389 v1(4170,7311) 4204,7345 4295,7345 4331,7381 4331,7551 4234,7648 ; v1(4045,8890) 3938,8890 3920,8908 3920,9548 ; v1(4084,7767) 4203,7648 4234,7648 ; v1(4234,7775) 4234,7648 ; v1(4387.5,9022.5) 4351,9059 v1(4351,9637.5) 4244.5,9637.5 4205,9677 4049,9677 3920,9548 ; v1(4571.5,9637.5) 4873.5,9637.5 4938,9702 4938,10117 v1(4982,10161) ; v1(4711,7369) 4578,7502 4578,7920 4657,7999 v1(4815,7999) 4815,8076 4835.5,8096.5 v1(5109.5,8096.5) 5615.5,8096.5 5771,7941 BOOT.2@6094,7941 BOOT.1@6194,7941 6233,7941 6258.2,7966.2 6258.2,8177.8 6237,8199 5536,8199 5494,8241 5494,8533 ; v1(4929,8757) 5204,8757 ; v1(5194,10156) 5326,10156 5371.06,10110.94 v1(5371.06,8883.06) 5371.06,8797.06 5331,8757 ; v1(5196.94,8992.94) 5196.94,8910.06 v1(5247,8860) ; v1(5304,8356) 5154,8356 5135.06,8374.94 v1(5135.06,8574.06) 5175,8614 5175,8728 5204,8757 ; P4.1@6228,8571 P4.3@6128,8571 P4.5@6028,8571 5532,8571 5494,8533 ; 3518,9548 3920,9548 ; 5204,8757 5331,8757 ; 5331,8757 5458,8757 5494,8721 5494,8533
VCC5: C25.1 C27.1 C28.2 K.2 K.5 P3.1 P3.3 P3.5 TFT_LCD.28 U2.3 U4.3 USB_OTG.1 | length 9421.4
  Top Layer w20: v2(4457,7228) 4644,7228 4762,7110 4829,7110 ; U4.3@4650.03,6879.94 4692.6,6922.5 C28.2@4780.06,6922.5 4780.06,7061.06 4829,7110 ; TFT_LCD.28@4890,10575 4890,10615 4916,10641 5270,10641 5308,10603 v2(5308,10543) ; C27.1@4950,7110 4829,7110 ; U2.3@5294,7113 5294,7161 5316,7183 C25.1@5443,7183 5587,7183 5664,7260 K.2@5724,7260 K.5@5936.6,7260 ; P3.1@6029,8261 P3.3@6129,8261 P3.5@6229,8261
  Bottom Layer w20: USB_OTG.1@3837.99,7109.06 3837.99,7180.99 3885,7228 4719,7228 4751,7260 K.2@5724,7260 K.5@5936.6,7260 6267,7260 6300,7293 6300,10305 6262,10343 5363,10343 5306,10400 v2@5306,10543 ; P3.1@6029,8261 P3.3@6129,8261 P3.5@6229,8261 6280,8261 6300,8241
VDDA: C10.2 C11.2 R3.1 U0.32 U0.33 | length 871.8
  Top Layer w10: U0.32@4911.74,8201.23 4857,8255.97 4857,8306 4886.5,8335.5 5107,8335.5 ; U0.33@4925.65,8215.15 4881,8259.81 4881,8301 4899,8319 5090.5,8319 5107,8335.5 ; R3.1@5244.5,8335.5 C10.2@5131.06,8335.5 5107,8335.5
pads on no net: BAT. JTAG.11 JTAG.17 JTAG.19 K.1 K.6 SD_CARD.10 SD_CARD.11 SD_CARD.12 TFT_LCD. TFT_LCD.32 U2.5 USB_OTG.4 USB_OTG.6 USB_OTG.7 USB_OTG.8 USB_OTG.9 USB_OTG.MH1 USB_OTG.MH2 USB_POWER.2 USB_POWER.3 USB_POWER.4 USB_POWER.6 USB_POWER.7 USB_POWER.8 USB_POWER.9 USB_POWER.MH1 USB_POWER.MH2 Y1.@5405.32,7910
copper on no net: | length 7982.3
  Top Layer w10: 2223,6755 2423,6755 ; 2223,10675 2423,10675 ; 2303,6815 2323,6755 ; 2303,10615 2323,10675 ; 2323,8434.09 2323,6755 ; 2323,8995.91 2323,10675 ; 2343,6815 2323,6755 ; 2343,10615 2323,10675 ; 2451,10705 2451,10905 ; 2511,10785 2451,10805 ; 2511,10825 2451,10805 ; 4110.09,10805 2451,10805 ; 4671.91,10805 6331,10805 ; 6271,10785 6331,10805 ; 6271,10825 6331,10805 ; 6331,10705 6331,10905

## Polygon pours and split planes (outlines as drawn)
GND on Bottom Layer "Top Layer-No Net" (solid, remove dead copper, pour order 14): 2445,10675 2445,6755 6335,6755 6335,10675 2445,10675
GND on Top Layer "Top Layer-No Net" (solid, remove dead copper, pour order 12): 2445,10675 2445,6755 6335,6755 6335,10675 2445,10675

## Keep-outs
Keep-Out Layer:
  the board outline again, w10

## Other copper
Top Layer:
  text "3880 (mil)" at 4120.09,10769.01 h60
  text "3920 (mil)" at 2358.99,8444.09 h60 r90

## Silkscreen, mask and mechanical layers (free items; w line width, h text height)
Top Overlay:
  text "7' LCD" at 2912,10615 h36
  text "4.3' LCD" at 3232,10605 h36
  text "PB12" at 5920,10265 h36
  text "PB15" at 5735,10261 h36
  text "PB13" at 5735,10164 h36
  text "PB14" at 5920,10164 h36
  text "PB0" at 5920,10070 h36
  text "PB1" at 5735,10062 h36
  text "PC5" at 5735,9968 h36
  text "PC4" at 5920,9964 h36
  text "PA3" at 5735,9870 h36
  text "PA2" at 5920,9866 h36
  text "PA1" at 5735,9763 h36
  text "PA0" at 5920,9762 h36
  text "PC3" at 5735,9664 h36
  text "PC2" at 5920,9663 h36
  text "PC0" at 5920,9565 h36
  text "PC1" at 5735,9562 h36
  text "PC13" at 5735,9467 h36
  text "PE6" at 5920,9463 h36
  text "PE4" at 5920,9364 h36
  text "PE5" at 5735,9363 h36
  text "PE3" at 5735,9263 h36
  text "PE2" at 5920,9261 h36
  text "PB7" at 5735,9162 h36
  text "PB6" at 5920,9160 h36
  text "PG15" at 5920,9066 h36
  text "PB5" at 5735,9062 h36
  text "PG13" at 5920,8964 h36
  text "PG14" at 5735,8959 h36
  text "PG8" at 2956,8943 h36
  text "PG7" at 2759,8940 h36
  text "PG11" at 5735,8865 h36
  text "PG9" at 5920,8865 h36
  text "PG6" at 2759,8843 h36
  text "PC6" at 2961,8843 h36
  text "PD6" at 5920,8764 h36
  text "PD7" at 5735,8762 h36
  text "PC7" at 2762,8748 h36
  text "PA8" at 2961,8745 h36
  text "GND" at 5920,8662 h36
  text "PD3" at 5735,8658 h36
  text "PA9" at 2767,8645 h36
  text "PA10" at 2962,8643 h36
  text "GND" at 5815,8451 h36
  text "GND" at 5818,8349 h36
  text "BOOT1" at 6022,7972 h36 r90
  text "BOOT0" at 6300,7954 h36 r90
